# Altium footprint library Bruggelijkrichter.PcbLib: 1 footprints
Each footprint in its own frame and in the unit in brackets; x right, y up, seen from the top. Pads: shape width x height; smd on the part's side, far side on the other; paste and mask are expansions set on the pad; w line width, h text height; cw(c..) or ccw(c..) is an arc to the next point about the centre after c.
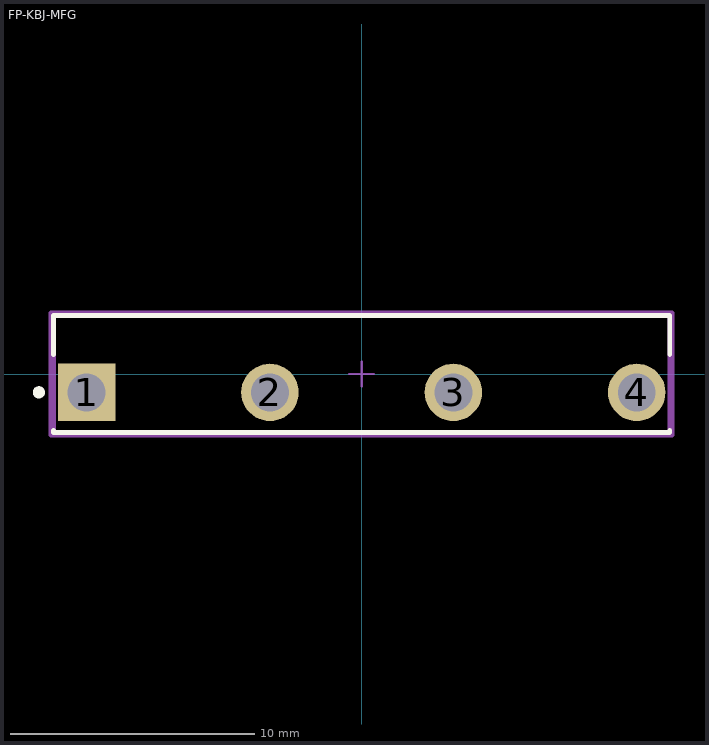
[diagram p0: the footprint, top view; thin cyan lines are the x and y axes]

## FP-KBJ-MFG [mm]
pads (4):
  rect 2.35x2.35 hole 1.55 paste-2539.97 mask+0: 1(-11.25,-0.75)
  round 2.35 hole 1.55 paste-2539.97 mask+0: 2(-3.75,-0.75) 3(3.75,-0.75) 4(11.25,-0.75)
Top Overlay:
  circle w0.25: c-13.2,-0.75 r0.125
  lines w0.2: -12.6,-2.3 -12.6,-2.4 12.6,-2.4 12.6,-2.3 ; -12.6,0.8 -12.6,2.4 12.6,2.4 12.6,0.8
Top Assembly:
  lines w0.2: -12.7,-2.5 -12.7,2.5 12.7,2.5 12.7,-2.5 -12.7,-2.5
  text ".Designator" at 0,0.188 h1
Top 3D Body:
  lines w0.2: -12.6,-2.4 -12.6,2.4 12.6,2.4 12.6,-2.4 -12.6,-2.4
Top Courtyard:
  lines w0.2: -12.7,-2.5 -12.7,2.5 12.7,2.5 12.7,-2.5 -12.7,-2.5
Top Component Center:
  lines w0.1: -0.5,0 0.5,0 ; 0,-0.5 0,0.5
3D body "Diode_Diodes_KBJ608G_eec.STEP": height 0.25, standoff 0, extent -12.7,-2.5 12.7,2.5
